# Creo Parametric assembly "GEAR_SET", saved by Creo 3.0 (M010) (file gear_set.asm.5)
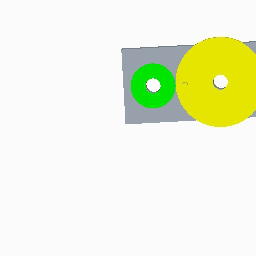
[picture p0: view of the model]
Units: millimeter Newton Second (mmNs); MM, TONNE, SECS

Created from: INLBS_ASM_DESIGN.ASM

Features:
  1. datum plane "ASM_RIGHT"
  2. datum plane "ASM_TOP"
  3. datum plane "ASM_FRONT"
  4. coordinate system
  5. coordinate system
  6. component "GEAR_BASE"
  7. component "GEAR001"
  8. component "GEAR002"

Other named items: ACS0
